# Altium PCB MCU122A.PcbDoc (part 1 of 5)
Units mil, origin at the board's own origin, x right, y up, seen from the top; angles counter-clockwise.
Board outline 4950 x 3450 mil, 4 copper layers (Top Layer, Signal Layer 1, Signal Layer 2, Bottom Layer), stack 60 mil thick; 257 components, 158 nets, 848 pads, 1971 vias.
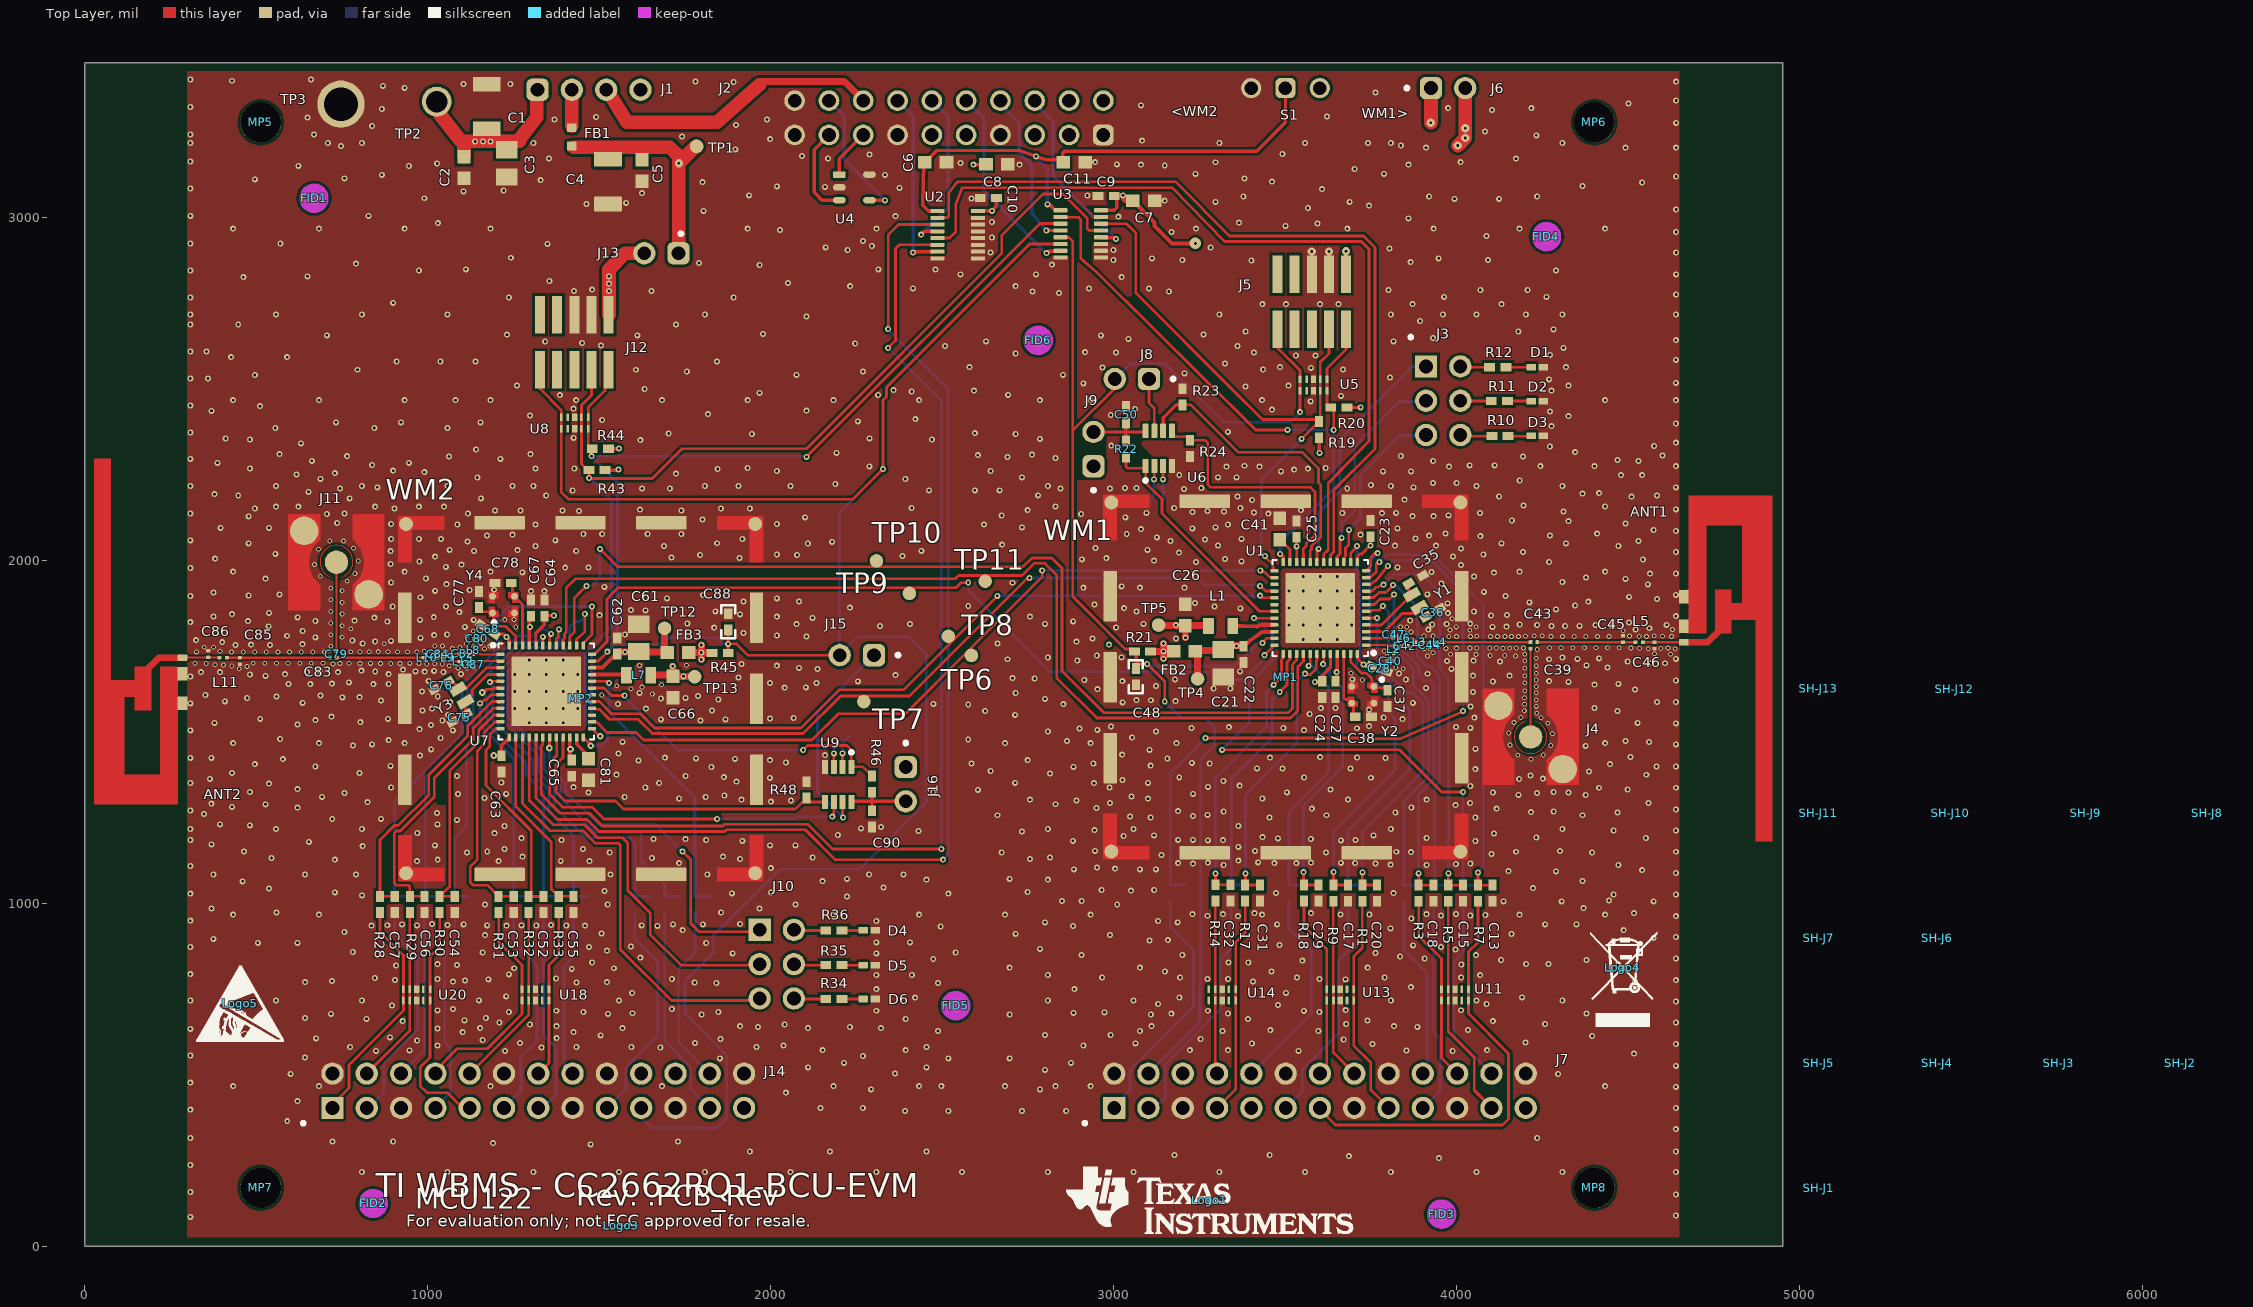
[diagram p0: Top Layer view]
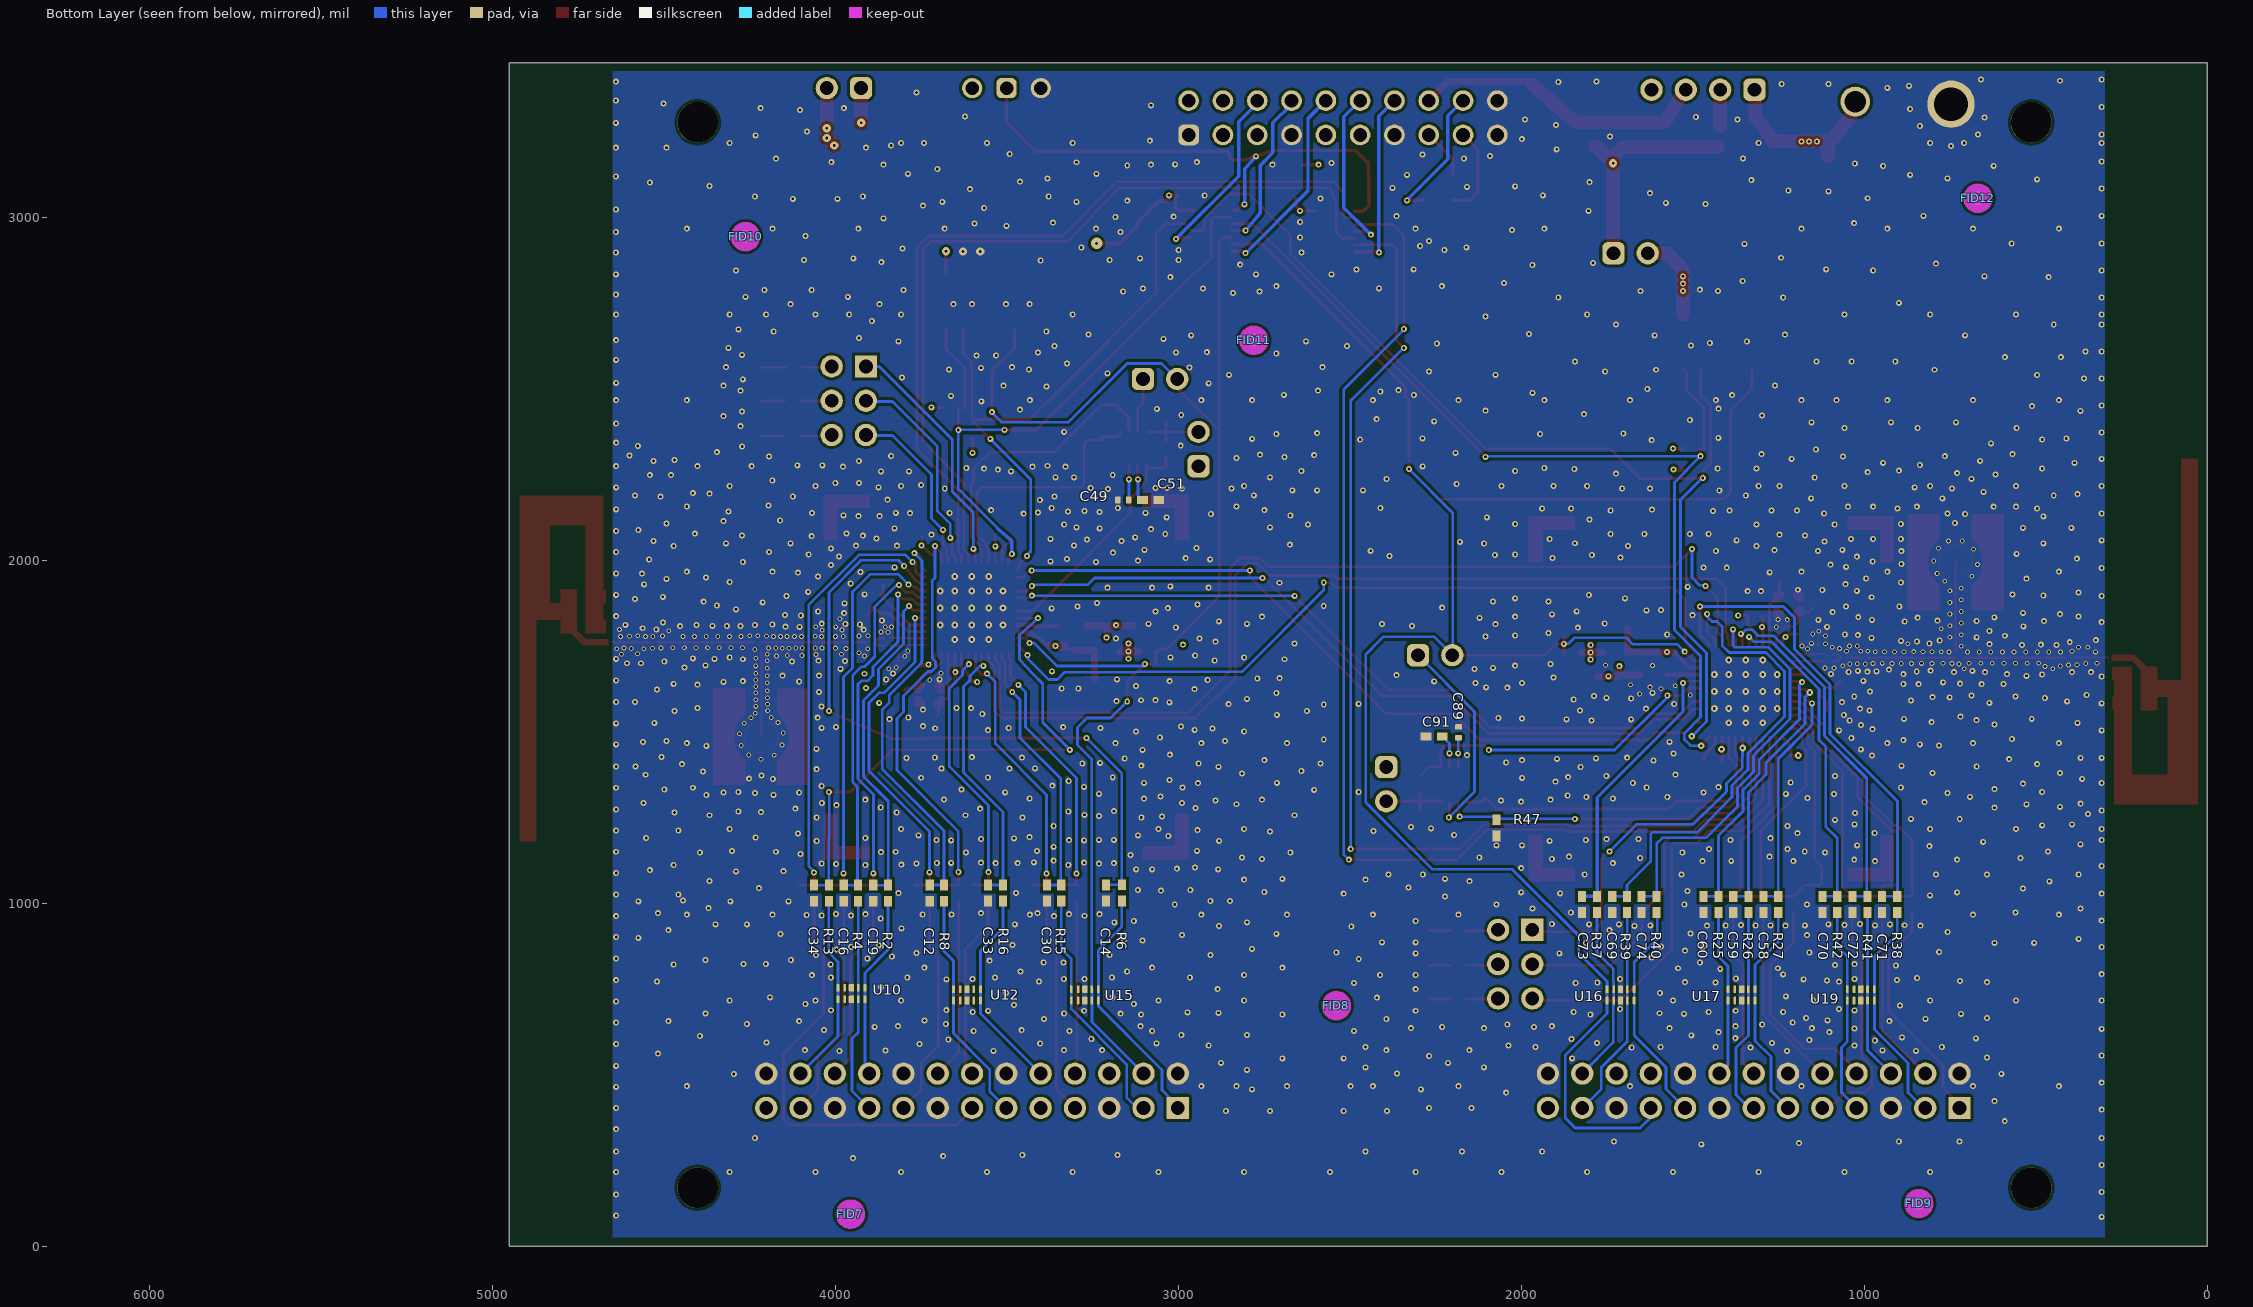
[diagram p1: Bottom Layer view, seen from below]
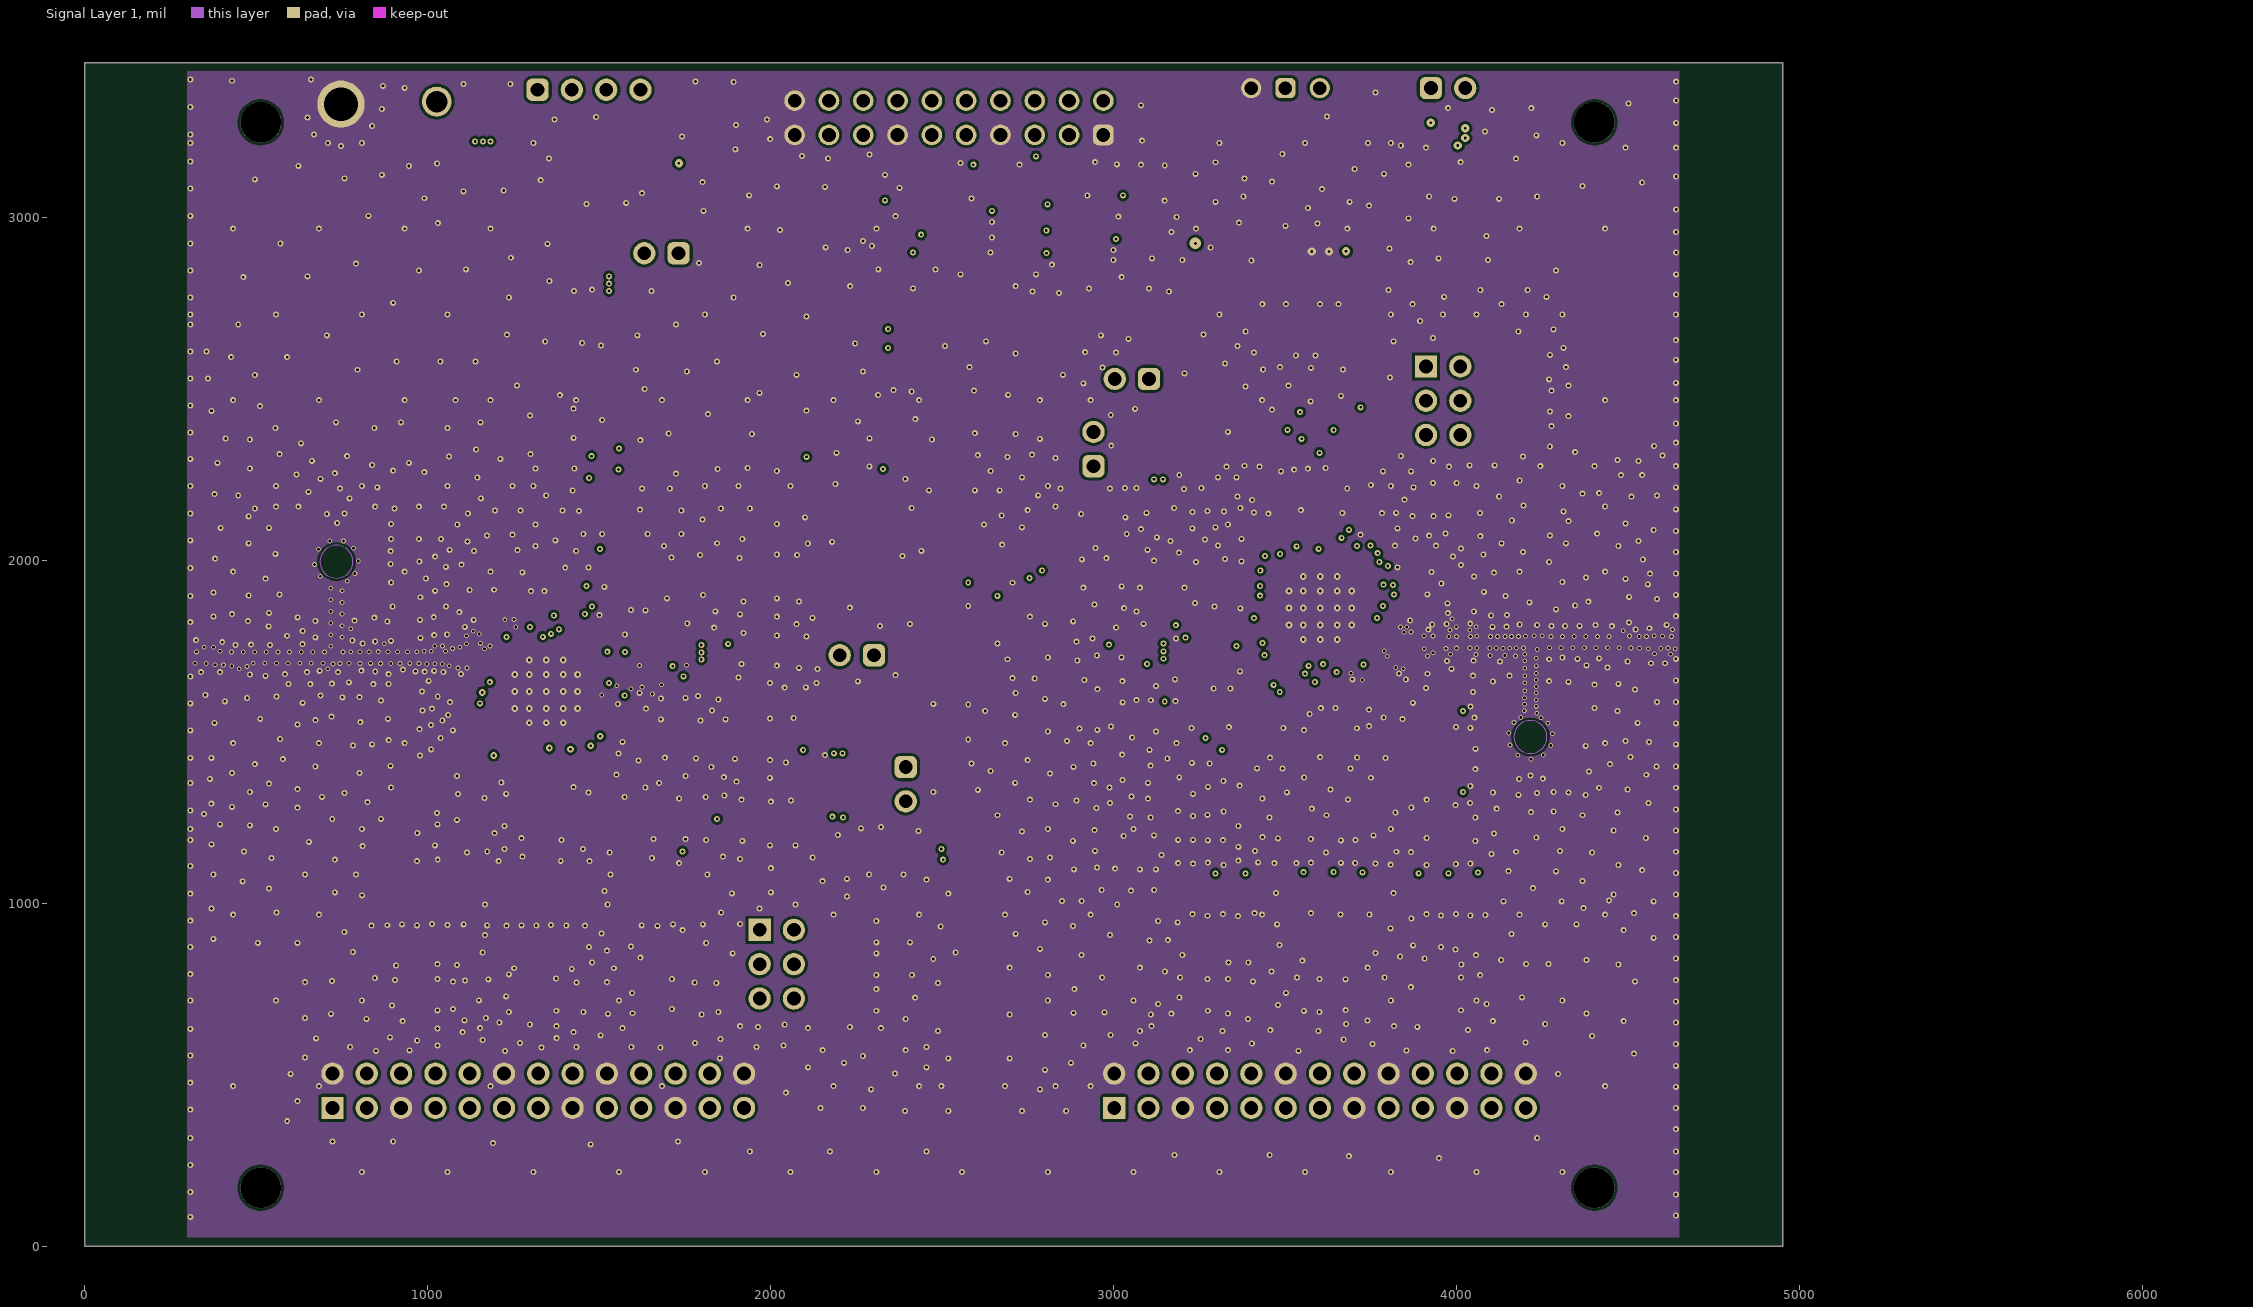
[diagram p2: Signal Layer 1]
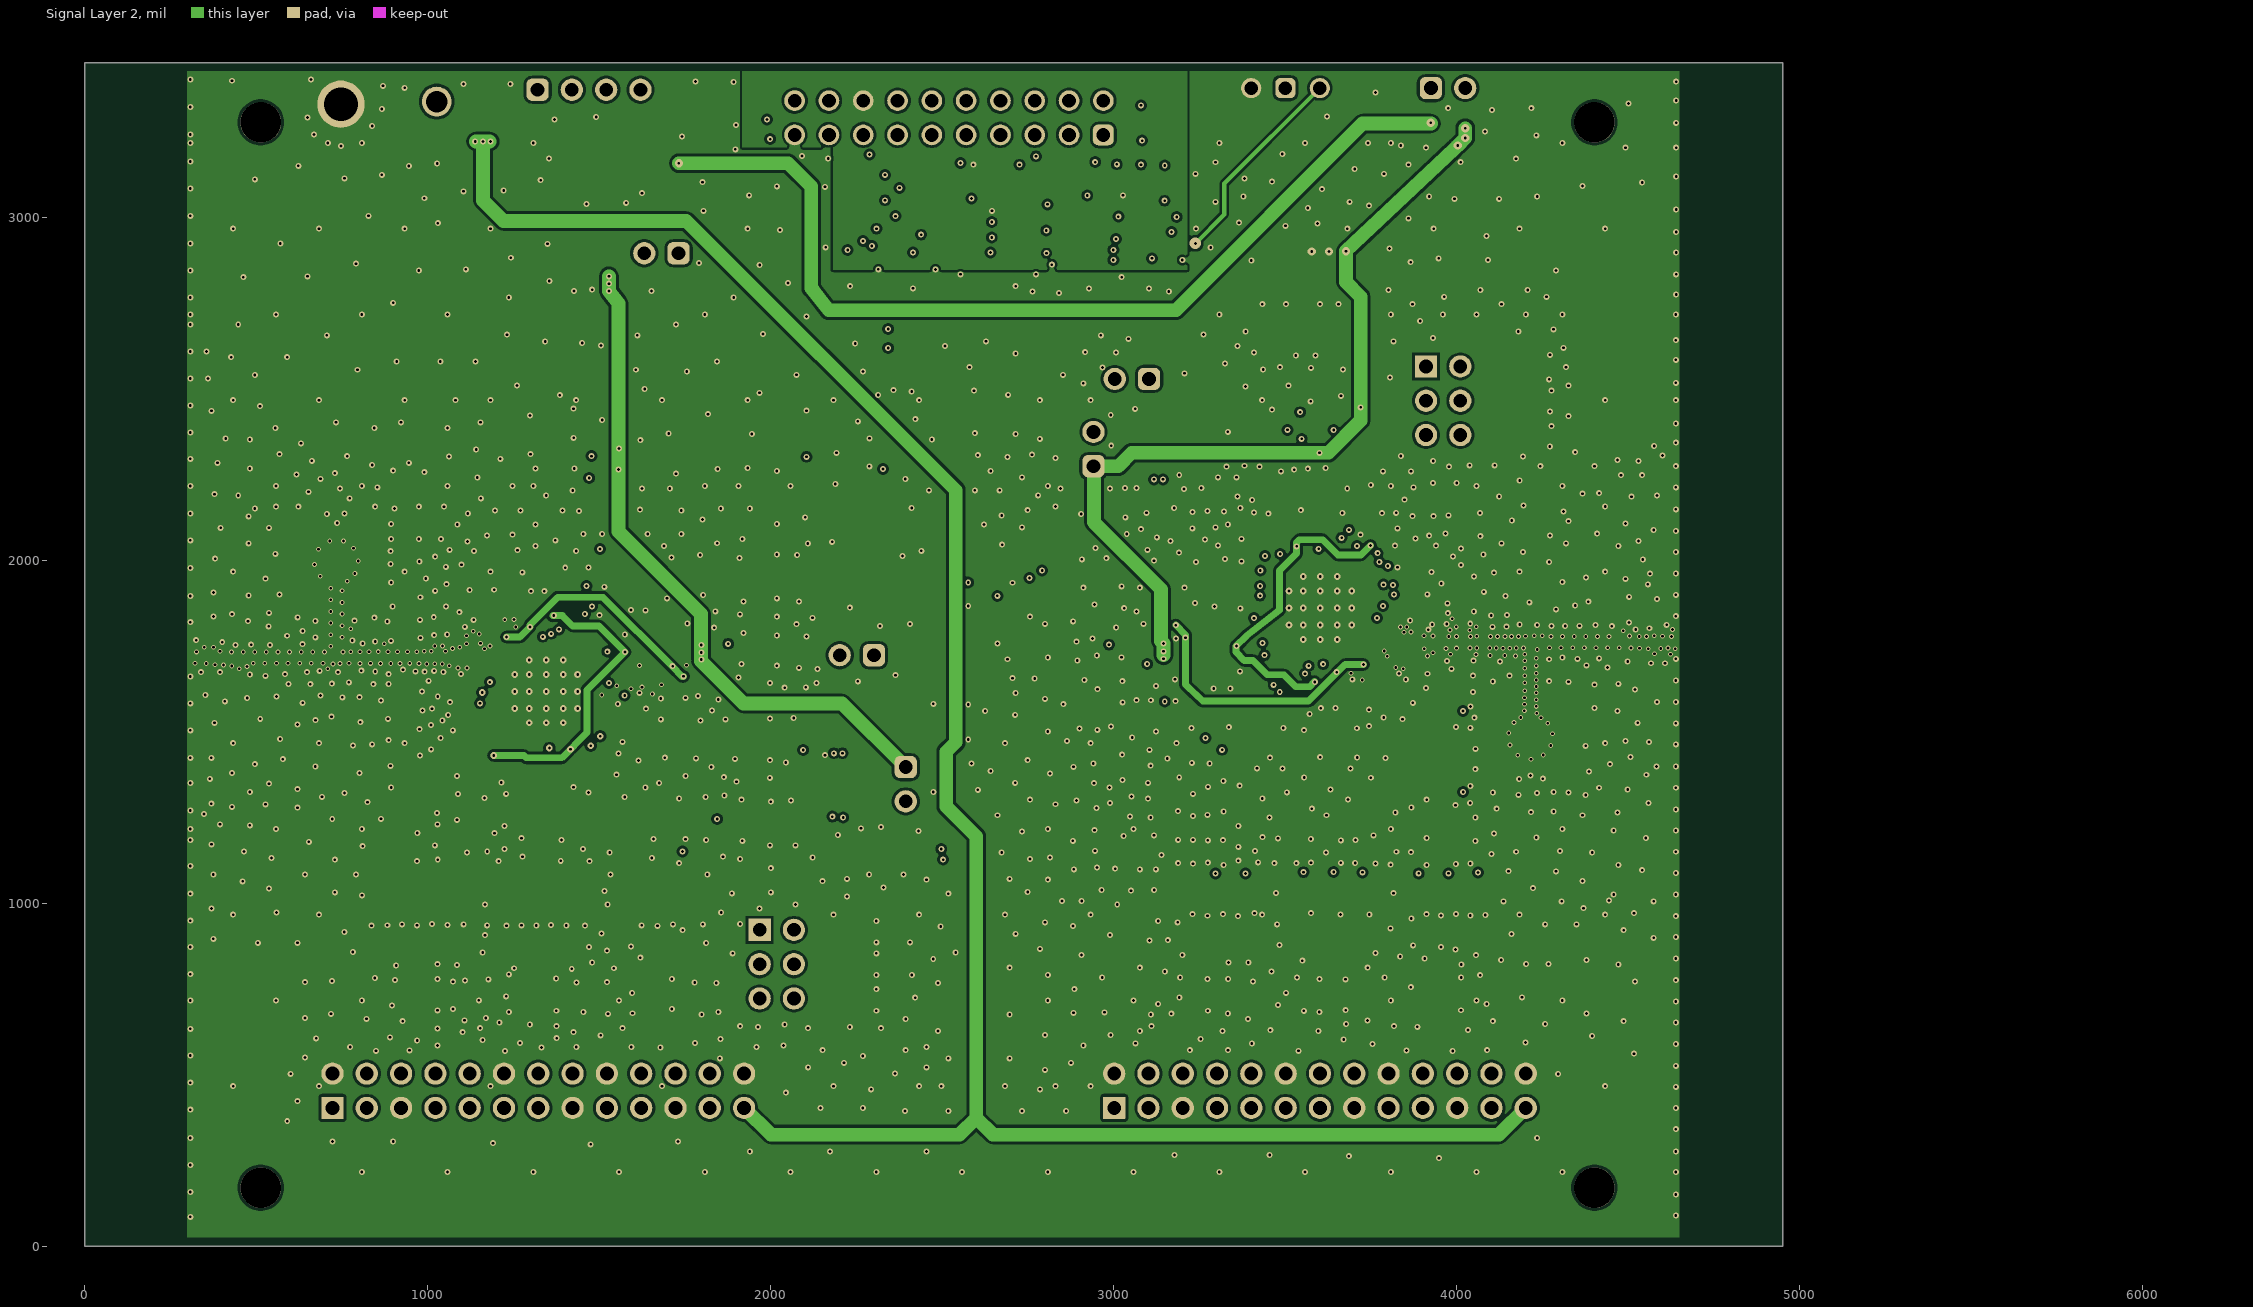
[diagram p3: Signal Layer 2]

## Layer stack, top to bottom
Top Solder: solder mask 1, Solder Resist, Dk 3.4
Top Layer: signal copper 1.6
Dielectric 1: prepreg 5, FR-4 High Tg, Dk 4.6
Signal Layer 1: signal copper 1.4
Dielectric 2: core 44, FR-4 High Tg, Dk 4.6
Signal Layer 2: signal copper 1.4
Dielectric 3: prepreg 5, FR-4 High Tg, Dk 4.6
Bottom Layer: signal copper 1.6
Bottom Solder: solder mask 1, Solder Resist, Dk 3.4

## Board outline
0,0 4950,0 4950,3450 0,3450

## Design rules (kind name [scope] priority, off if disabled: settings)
AcuteAngle [All] p1: minimum=4.50000000000000E+0001 checktracksonly=FALSE
AssemblyTestPointUsage [All] p1: valid=2
BoardOutlineClearance BoardOutlineClearance_MountingHoles [OnCopper and InComponentClass('Mounting Holes')] p1: gap=39.37 ignorepadtopadclearanceinfootprint=FALSE
BoardOutlineClearance BoardOutlineClearance_Poly [OnCopper and IsPoly] p2: gap=25 ignorepadtopadclearanceinfootprint=FALSE
BoardOutlineClearance [OnCopper and Not InComponentClass('Logo') and not InComponentClass('FiducialMark') and not InRegion(1000,500,4000,800) and not InPoly] p3: gap=30 ignorepadtopadclearanceinfootprint=FALSE
Clearance RF_GND_Clearance [InNetClass('RF') vs InNet('GND')] p1: gap=6.07 ignorepadtopadclearanceinfootprint=TRUE
Clearance Clearance_1 [All] p2: gap=7.87 ignorepadtopadclearanceinfootprint=TRUE
Clearance Clearance_FiducialMark [IsKeepOut and InComponentClass('FiducialMark') vs IsPad and InComponentClass('FiducialMark')] p3: gap=0 ignorepadtopadclearanceinfootprint=TRUE
Clearance Clearance_Keepouts [((IsTrack Or IsArc) And Not InPoly) And IsFree and IsKeepOut vs ((IsTrack Or IsArc) And Not InPoly) And IsFree and IsKeepOut] p4: gap=0 ignorepadtopadclearanceinfootprint=TRUE
ComponentClearance ComponentClearance_MountingHoles_FiducialMarks [InComponentClass('Mounting Holes') vs InComponentClass('FiducialMark')] p1: gap=50 collisioncheckmode=3 verticalgap=10 showdistances=FALSE
ComponentClearance ComponentClearance_Shunt [InComponentClass('Header') vs InComponentClass('Shunt')] p2: gap=0 collisioncheckmode=3 verticalgap=0 showdistances=FALSE
ComponentClearance ComponentClearance_Logo [InComponentClass('Logo')] p3: gap=30 collisioncheckmode=3 verticalgap=10 showdistances=FALSE
ComponentClearance ComponentClearance_ScrewToNut [(HasFootprint('NY PMS 440 0025 PH')) vs (HasFootprint('Keystone_1902C'))] p4: gap=5 collisioncheckmode=3 verticalgap=10 showdistances=FALSE
ComponentClearance ComponentClearance_MountingHoles [InComponentClass('Mounting Holes')] p5: gap=100 collisioncheckmode=3 verticalgap=100000 showdistances=FALSE
ComponentClearance ComponentClearance_SmallPassives [HasFootprint('0201*') or HasFootprint('0402*') or HasFootprint('0508') or HasFootprint('0603*') or HasFootprint('0612') or HasFootprint('0805*') or HasFootprint('0815*') or HasFootprint('0830*') or HasFootprint('1206*') or HasFootprint('1210*') or HasFootprint('1808*') or HasFootprint('1812*') or HasFootprint('1825*') or HasFootprint('2010*') or HasFootprint('2220*') or HasFootprint('2225*') or HasFootprint('2512*') or HasFootprint('2728*') or HasFootprint('3518*') vs HasFootprint('0201*') or HasFootprint('0402*') or HasFootprint('0508') or HasFootprint('0603*') or HasFootprint('0612') or HasFootprint('0805*') or HasFootprint('0815*') or HasFootprint('0830*') or HasFootprint('1206*') or HasFootprint('1210*') or HasFootprint('1808*') or HasFootprint('1812*') or HasFootprint('1825*') or HasFootprint('2010*') or HasFootprint('2220*') or HasFootprint('2225*') or HasFootprint('2512*') or HasFootprint('2728*') or HasFootprint('3518*')] p6: gap=14.96 collisioncheckmode=3 verticalgap=10 showdistances=FALSE
ComponentClearance ComponentClearance_THtoSMT [IsThruComponent vs IsSMTComponent] p7: gap=30 collisioncheckmode=3 verticalgap=30 showdistances=FALSE
ComponentClearance ComponentClearance_THtoTH [IsThruComponent vs IsThruComponent] p8: gap=20 collisioncheckmode=3 verticalgap=30 showdistances=FALSE
ComponentClearance [All] p9: gap=10 collisioncheckmode=3 verticalgap=10 showdistances=FALSE
DiffPairsRouting [All] p1: maxlimit=100 minlimit=10 mostfreqgap=10 toplayer_minwidth=15 toplayer_maxwidth=15 toplayer_prefwidth=15 midlayer1_minwidth=15 midlayer1_maxwidth=15 midlayer1_prefwidth=15 midlayer2_minwidth=15 midlayer2_maxwidth=15 midlayer2_prefwidth=15 bottomlayer_minwidth=15 bottomlayer_maxwidth=15 bottomlayer_prefwidth=15 maxuncoupledlength=1000
FabricationTestPointUsage TestPointUsage [All] p1: valid=2 allowmultiple=FALSE
FabricationTestpoint Testpoint [All] p1: side=3 testpointundercomponent=TRUE minsize=40 maxsize=100 preferedsize=60 minholesize=0 maxholesize=40 preferedholesize=32 testpointgrid=1 allowsidetop=TRUE allowsidebottom=TRUE usegrid=TRUE gridtolerance=0.01
FanoutControl Fanout_LCC [IsLCC] p1: bgadir=Out bgaviamode=Centered fanoutstyle=Auto fanoutdirection=Alternating viagrid=1 // Fanout_LCC (Default Rule)
FanoutControl Fanout_BGA [IsBGA] p2: bgadir=Out bgaviamode=Centered fanoutstyle=Auto fanoutdirection=Alternating viagrid=1 // Fanout_BGA (Default Rule)
FanoutControl Fanout_Default [All] p4: bgadir=Out bgaviamode=Centered fanoutstyle=Auto fanoutdirection=Alternating viagrid=1 // Fanout_Default (Default Rule)
FanoutControl Fanout_Small [(CompPinCount < 5)] p5: bgadir=Out bgaviamode=Centered fanoutstyle=Auto fanoutdirection=OutThenIn viagrid=1 // Fanout_Small (Default Rule)
HoleSize [All] p1: absolutevalues=TRUE maxlimit=251 minlimit=8 maxpercent=80.000 minpercent=20.000
MinimumAnnularRing MinimumAnnularRing_ThermalPadVias [IsVia and InAnyComponent] p1: minimumring=5.9
MinimumAnnularRing [All] p2: minimumring=2.9
MinimumSolderMaskSliver MinimumSolderMaskSliver_Logo [InComponentClass('Logo') vs InComponentClass('Logo')] p1: minsoldermaskwidth=0.7
MinimumSolderMaskSliver [All] p2: minsoldermaskwidth=3.94
PlaneClearance PlaneClearance_1 [All] p1: clearance=20
PlaneClearance [InNet('3V3_XDS') And OnLayer('Signal Layer 2')] p2: clearance=0
PlaneConnect [InNet('3V3_XDS') And OnLayer('Signal Layer 2')] p1: planeconnectstyle=Direct reliefexpansion=10 reliefentries=4 reliefconductorwidth=10 reliefairgap=10
PlaneConnect PlaneConnect_1 [All] p2: planeconnectstyle=Direct reliefexpansion=20 reliefentries=4 reliefconductorwidth=10 reliefairgap=10
PolygonConnect [All] p1: connectstyle=Direct reliefconductorwidth=10 reliefentries=4 polygonreliefangle="90 Angle" airgapwidth=10
RoutingVias ThermalPadVias [IsVia and InAnyComponent] p1: holewidth=7.87 width=19.68 viastyle="Through Hole" minholewidth=5.87 minwidth=11.4 maxholewidth=12.99 maxwidth=23.62
RoutingVias [All] p2: holewidth=16 width=34 viastyle="Through Hole" minholewidth=5.87 minwidth=11.4 maxholewidth=40 maxwidth=65
SilkToBoardRegionClearance [Not ((IsComment or IsDesignator) And (Hide <> 'False')) and not InRegion(1000,500,4000,800)] p1:
SilkToSilkClearance SilkToSilkClearance_Pb-FreeLogo [(HasFootprint('Pb-Free_Overlay_Medium') OR HasFootprint('Pb-Free_Overlay_Small')) vs (HasFootprint('Pb-Free_Overlay_Medium') OR HasFootprint('Pb-Free_Overlay_Small'))] p1: silktosilkclearance=0
SilkToSilkClearance [All] p2: silktosilkclearance=3.94
SilkToSolderMaskClearance SilkToComponentPadClearance [(IsPad or IsFill or IsRegion) and InAnycomponent] p1: minsilkscreentomaskgap=5 clearancetoexposedcopper=TRUE
SilkToSolderMaskClearance "Silk to Solder Mask Opening" [All] p2: minsilkscreentomaskgap=3.94 clearancetoexposedcopper=FALSE
SolderMaskExpansion SolderMaskExpansion_2 [InPadClass('All Pads')] p1 off: expansion=8 istentingtop=FALSE
SolderMaskExpansion SolderMaskExpansion_1 [IsVia] p2: expansion=4 istentingtop=TRUE
SolderMaskExpansion [All] p3 off: expansion=-20 istentingtop=TRUE soldermaskfromhole=TRUE
SupplyNets "Schematic Supply Nets_13" [InNet('VDDR_WM2')] p1: voltage=0.000
SupplyNets "Schematic Supply Nets_12" [InNet('5V0_BP')] p2: voltage=0.000
SupplyNets "Schematic Supply Nets_11" [InNet('3V3_WM')] p3: voltage=0.000
SupplyNets "Schematic Supply Nets_10" [InNet('VDDS_WM2')] p4: voltage=0.000
SupplyNets "Schematic Supply Nets_9" [InNet('WM2_VDD')] p5: voltage=0.000
SupplyNets "Schematic Supply Nets_8" [InNet('3V3_XDS')] p6: voltage=0.000
SupplyNets "Schematic Supply Nets_7" [InNet('3V3_EXT')] p7: voltage=0.000
SupplyNets "Schematic Supply Nets_6" [InNet('VDDS_WM1')] p8: voltage=0.000
SupplyNets "Schematic Supply Nets_5" [InNet('WM1_WD_VDD')] p9: voltage=0.000
SupplyNets "Schematic Supply Nets_4" [InNet('3V3_VDD')] p10: voltage=0.000
SupplyNets "Schematic Supply Nets_3" [InNet('VDDR_WM1')] p11: voltage=0.000
SupplyNets "Schematic Supply Nets_2" [InNet('GND')] p12: voltage=0.000
SupplyNets "Schematic Supply Nets_1" [InNet('WM1_VDD')] p13: voltage=0.000
SupplyNets "Schematic Supply Nets" [InNet('WM2_WD_VDD')] p14: voltage=0.000
UnRoutedNet [All] p1 off: checkbadconnections=TRUE
Width RF [InNetClass('RF')] p1: maxlimit=6.5 minlimit=3.56 preferedwidth=6.5 toplayer_minwidth=6.5 midlayer1_maxwidth=3.68 midlayer1_prefwidth=3.68 midlayer2_maxwidth=3.68 midlayer2_prefwidth=3.68 bottomlayer_minwidth=6.5 impedanceprofiledriven=TRUE impedanceprofileid={6BF253D9-752C-47ED-B3CD-644EDC811900} impedanceprofilevalue=50.000000 minimp=50.000000 maximp=50.000000 favimp=50.000000 checkconnectedcopper=TRUE
Width [All] p2: maxlimit=100 minlimit=4 preferedwidth=10 midlayer1_minwidth=6 midlayer2_minwidth=6 bottomlayer_minwidth=6 minimp=50.000000 maximp=50.000000 favimp=50.000000 checkconnectedcopper=TRUE
13 further rules are at their usual default settings.

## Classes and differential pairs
component class MCU122A_WM2_ESD: U16 U17 U18 U19 U20
component class MCU122A_WM1_ESD: U10 U11 U12 U13 U14 U15
net class RF: NetANT1_1 NetANT2_1 NetC39_1 NetC39_2 NetC40_1 NetC42_2 NetC43_2 NetC44_2 NetC79_1 NetC79_2 NetC82_2 NetC83_2 NetC84_2 WM1_RF1_N WM1_RF1_P WM2_RF1_N WM2_RF1_P
component class MCU122A_WM2_GPIO_Header: C89 C90 C91 J14 J15 J16 R46 R47 R48 SH-J12 SH-J13 U9
component class MCU122A_WM2: ANT2 C52 C53 C54 C55 C56 C57 C58 C59 C60 C61 C62 C63 C64 C65 C66 C67 C68 C69 C70 C71 C72 C73 C74 C75 C76 C77 C78 C79 C80 C81 C82 C83 C84 C85 C86 C87 C88 D4 D5 D6 FB3 J10 J11 J12 J13 L7 L8 L9 L10 L11 L12 R25 R26 R27 R28 R29 R30 R31 R32 R33 R34 R35 R36 R37 R38 R39 R40 R41 R42 R43 R44 R45 SH-J8 SH-J9 SH-J10 SH-J11 TP12 TP13 U7 U8 Y3 Y4
component class MCU122A_Hardware: FID1 FID2 FID3 FID4 FID5 FID6 FID7 FID8 FID9 FID10 FID11 FID12 Logo1 Logo3 Logo4 Logo5 MP1 MP2 MP3 MP4 MP5 MP6 MP7 MP8 ZZ1 ZZ2 ZZ3 ZZ4
component class MCU122A_WM1_GPIO_Header: C49 C50 C51 J7 J8 J9 R22 R23 R24 SH-J6 SH-J7 U6
component class MCU122A_WM1: ANT1 C12 C13 C14 C15 C16 C17 C18 C19 C20 C21 C22 C23 C24 C25 C26 C27 C28 C29 C30 C31 C32 C33 C34 C35 C36 C37 C38 C39 C40 C41 C42 C43 C44 C45 C46 C47 C48 D1 D2 D3 FB2 J3 J4 J5 J6 L1 L2 L3 L4 L5 L6 R1 R2 R3 R4 R5 R6 R7 R8 R9 R10 R11 R12 R13 R14 R15 R16 R17 R18 R19 R20 R21 SH-J2 SH-J3 SH-J4 SH-J5 TP4 TP5 TP6 TP7 TP8 TP9 TP10 TP11 U1 U5 Y1 Y2
component class MCU122A_Connector_PWR: C1 C2 C3 C4 C5 C6 C7 C8 C9 C10 C11 FB1 J1 J2 S1 SH-J1 TP1 TP2 TP3 U2 U3 U4

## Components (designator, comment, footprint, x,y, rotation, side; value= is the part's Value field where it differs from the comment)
ANT1 "Inverted F Antenna" 0-MFG 4783.46,1684.37 r270 top
ANT2 "Inverted F Antenna" 0-MFG 164.08,1791.31 r90 top
C1 "GCM32ER71E106MA57L" FP-GCM32ER71E106MA57L_1210-MFG 1172.33,3322.3 r270 top value=10µF
C2 "GCM188R71C105KA64D" 0603 1105.83,3144.43 r270 top value=1uF
C3 "GCM21BD70J226ME36L" 0805_HV 1230.94,3156.37 r270 top value=22uF
C4 "GCM32ER71E106MA57L" FP-GCM32ER71E106MA57L_1210-MFG 1525.59,3103.35 r90 top value=10µF
C5 "GCM188R71C105KA64D" 0603 1624.51,3136.04 r270 top value=1uF
C6 "GCM188R71C105KA64D" 0603 2659.22,3153.84 r180 top value=1uF
C7 "GCM188R71C105KA64D" 0603 3087.6,3047.58 r180 top value=1uF
C8 "GCM155R71A104KA55D" 0402 2634.61,3055.07 r0 top value=0.1uF
C9 "GCM155R71A104KA55D" 0402 2978,3060.88 r0 top value=0.1uF
C10 "GCM188R71C105KA64D" 0603 2481.07,3160 r0 top value=1uF
C11 "GCM188R71C105KA64D" 0603 2885.12,3160 r0 top value=1uF
C12 "GCM155R71A104KA55D" 0402 3724.6,1028.97 r90 bottom value=0.1uF
C13 "GCM155R71A104KA55D" 0402 4104.69,1028.6 r90 top value=0.1uF
C14 "GCM155R71A104KA55D" 0402 3211.37,1029.38 r90 bottom value=0.1uF
C15 "GCM155R71A104KA55D" 0402 4018.55,1028.6 r90 top value=0.1uF
C16 "GCM155R71A104KA55D" 0402 3975.42,1028.6 r90 bottom value=0.1uF
C17 "GCM155R71A104KA55D" 0402 3683.42,1028.97 r270 top value=0.1uF
C18 "GCM155R71A104KA55D" 0402 3932.79,1028.6 r90 top value=0.1uF
C19 "GCM155R71A104KA55D" 0402 3889.51,1028.6 r90 bottom value=0.1uF
C20 "GCM155R71A104KA55D" 0402 3767.47,1028.97 r90 top value=0.1uF
C21 "GCM21BD70J226ME36L" 0805_HV 3319.9,1699.18 r270 top value=22uF
C22 "GCM155R71A104KA55D" 0402 3377.97,1724.77 r270 top value=0.1uF
C23 "GCM155R71A104KA55D" 0402 3749.03,2091.54 r90 top value=0.1uF
C24 "GCM155R71A104KA55D" 0402 3608,1623 r270 top value=0.1uF
C25 "GCM155R71A104KA55D" 0402 3533.46,2090 r90 top value=0.1uF
C26 "AMK107BBJ226MAHT" 0603 3208.54,1839.48 r90 top value=22uF
C27 "GCM155R71A104KA55D" 0402 3647,1623 r270 top value=0.1uF
C28 "GCM155R71A104KA55D" 0402 3774.41,1683 r340 top value=0.1uF
C29 "GCM155R71A104KA55D" 0402 3597.41,1029.16 r90 top value=0.1uF
C30 "GCM155R71A104KA55D" 0402 3382.95,1029.16 r90 bottom value=0.1uF
C31 "GCM155R71A104KA55D" 0402 3426.45,1029.16 r90 top value=0.1uF
C32 "GCM155R71A104KA55D" 0402 3340.52,1029.57 r90 top value=0.1uF
C33 "GCM155R71A104KA55D" 0402 3554.46,1029.16 r90 bottom value=0.1uF
C34 "GCM155R71A104KA55D" 0402 4061.83,1028.6 r90 bottom value=0.1uF
C35 "GCM1555C1H120JA16J" 0402 3881,1943 r30 top value=12pF
C36 "GCM1555C1H120JA16J" 0402 3930,1846.33 r30 top value=12pF
C37 "GCM1555C1H120JA16J" 0402 3798,1597 r270 top value=12pF
C38 "GCM1555C1H120JA16J" 0402 3728,1543 r0 top value=12pF
C39 "GCQ0335C1H1R0BB01D" FP-GCQ0335C1H1R0BB01D_0201-MFG 4215.44,1751.2 r270 top value=1pF
C40 "GCQ0335C1H120GB01D" FP-GCQ0335C1H120GB01D_0201-MFG 3806.5,1705 r180 top value=12pF
C41 "GCM188R71C105KA64D" 0603 3484.17,2090 r90 top value=1uF
C42 "GCQ0335C1H1R0WB01D" FP-GCQ0335C1H1R0WB01D_0201-MFG 3848,1749.3 r0 top value=1pF
C43 "GCQ0335C1H120GB01D" FP-GCQ0335C1H120GB01D_0201-MFG 4225.79,1760.54 r0 top value=12pF
C44 "GCQ0335C1H1R0WB01D" FP-GCQ0335C1H1R0WB01D_0201-MFG 3922,1751 r90 top value=1pF
C45 "GCQ0335C1HR70WB01D" FP-GCQ0335C1HR70WB01D_0201-MFG 4484.8,1769.9 r270 top value=0.7pF
C46 "GCQ0335C1H1R0BB01D" FP-GCQ0335C1H1R0BB01D_0201-MFG 4576.77,1751 r90 top value=1pF
C47 "GCQ0335C1H1R0WB01D" FP-GCQ0335C1H1R0WB01D_0201-MFG 3816.03,1782.5 r270 top value=1pF
C48 "GCM155R71A104KA55D" 0402 3064.77,1659.87 r270 top value=0.1uF
C49 "GCM155R71E473KA55D" FP-GCM155R71E473KA55D_0402-MFG 3160.62,2175.16 r0 bottom value=47nF
C50 "GCM155R71A104KA55D" 0402 3036.11,2423.59 r90 top value=0.1uF
C51 "GCM155R71E103KA37D" 0402 3080.71,2175.16 r180 bottom value=0.01uF
C52 "GCM155R71A104KA55D" 0402 1337.97,995.82 r90 top value=0.1uF
C53 "GCM155R71A104KA55D" 0402 1250.97,995.82 r90 top value=0.1uF
C54 "GCM155R71A104KA55D" 0402 1078.97,995.82 r90 top value=0.1uF
C55 "GCM155R71A104KA55D" 0402 1424.97,995.82 r270 top value=0.1uF
C56 "GCM155R71A104KA55D" 0402 990.97,995.82 r90 top value=0.1uF
C57 "GCM155R71A104KA55D" 0402 903.97,995.82 r90 top value=0.1uF
C58 "GCM155R71A104KA55D" 0402 1293.97,995.82 r90 bottom value=0.1uF
C59 "GCM155R71A104KA55D" 0402 1381.97,995.82 r90 bottom value=0.1uF
C60 "GCM155R71A104KA55D" 0402 1468.97,995.82 r90 bottom value=0.1uF
C61 "GCM21BD70J226ME36L" 0805_HV 1615.24,1772.86 r90 top value=22uF
C62 "GCM155R71A104KA55D" 0402 1552.78,1749.51 r90 top value=0.1uF
C63 "GCM155R71A104KA55D" 0402 1214.77,1405.74 r270 top value=0.1uF
C64 "GCM155R71A104KA55D" 0402 1340,1860 r90 top value=0.1uF
C65 "GCM155R71A104KA55D" 0402 1420,1393 r270 top value=0.1uF
C66 "AMK107BBJ226MAHT" 0603 1714.71,1629.43 r270 top value=22uF
C67 "GCM155R71A104KA55D" 0402 1301,1860 r90 top value=0.1uF
C68 "GCM155R71A104KA55D" 0402 1175.5,1798 r145 top value=0.1uF
C69 "GCM155R71A104KA55D" 0402 1734.97,995.82 r90 bottom value=0.1uF
C70 "GCM155R71A104KA55D" 0402 1121.73,995.82 r90 bottom value=0.1uF
C71 "GCM155R71A104KA55D" 0402 947.97,995.82 r90 bottom value=0.1uF
C72 "GCM155R71A104KA55D" 0402 1034.97,995.82 r90 bottom value=0.1uF
C73 "GCM155R71A104KA55D" 0402 1822.87,995.82 r90 bottom value=0.1uF
C74 "GCM155R71A104KA55D" 0402 1649.15,995.82 r90 bottom value=0.1uF
C75 "GCM1555C1H120JA16J" 0402 1092.6,1539.7 r210 top value=12pF
C76 "GCM1555C1H120JA16J" 0402 1040,1634 r210 top value=12pF
C77 "GCM1555C1H120JA16J" 0402 1149.5,1885 r90 top value=12pF
C78 "GCM1555C1H120JA16J" 0402 1220,1933.5 r180 top value=12pF
C79 "GCQ0335C1H1R0BB01D" FP-GCQ0335C1H1R0BB01D_0201-MFG 734,1724.7 r90 top value=1pF
C80 "GCQ0335C1H120GB01D" FP-GCQ0335C1H120GB01D_0201-MFG 1142.8,1770 r0 top value=12pF
C81 "GCM188R71C105KA64D" 0603 1468.5,1389 r270 top value=1uF
C82 "GCQ0335C1H1R0WB01D" FP-GCQ0335C1H1R0WB01D_0201-MFG 1101.6,1726.45 r180 top value=1pF
C83 "GCQ0335C1H120GB01D" FP-GCQ0335C1H120GB01D_0201-MFG 723.65,1715.3 r180 top value=12pF
C84 "GCQ0335C1H1R0WB01D" FP-GCQ0335C1H1R0WB01D_0201-MFG 1029,1724.75 r270 top value=1pF
C85 "GCQ0335C1HR70WB01D" FP-GCQ0335C1HR70WB01D_0201-MFG 452.23,1705.5 r90 top value=0.7pF
C86 "GCQ0335C1H1R0BB01D" FP-GCQ0335C1H1R0BB01D_0201-MFG 360.23,1726 r270 top value=1pF
C87 "GCQ0335C1H1R0WB01D" FP-GCQ0335C1H1R0WB01D_0201-MFG 1133.36,1694.77 r90 top value=1pF
C88 "GCM155R71A104KA55D" 0402 1876.19,1820.04 r90 top value=0.1uF
C89 "GCM155R71E473KA55D" FP-GCM155R71E473KA55D_0402-MFG 2183,1497.64 r90 bottom value=47nF
C90 "GCM155R71A104KA55D" 0402 2295.28,1245.36 r270 top value=0.1uF
C91 "GCM155R71E103KA37D" 0402 2253.84,1485.9 r0 bottom value=0.01uF
D1 "APHHS1005LZGCK-V" FP-APHHS1005LZGCK-V_0402-MFG 4235.14,2562.21 r180 top
D2 "APHHS1005LSECK/J4-PF" FP-APHHS1005LSECK/J4-PF_0402-MFG 4235.14,2462.71 r180 top
D3 "APHHS1005LSECK/J3-PF" FP-APHHS1005LSECK/J3-PF_0402-MFG 4234.77,2362.21 r180 top
D4 "APHHS1005LZGCK-V" FP-APHHS1005LZGCK-V_0402-MFG 2287.19,920.49 r180 top
D5 "APHHS1005LSECK/J4-PF" FP-APHHS1005LSECK/J4-PF_0402-MFG 2287.19,818.9 r180 top
D6 "APHHS1005LSECK/J3-PF" FP-APHHS1005LSECK/J3-PF_0402-MFG 2287.19,720.48 r180 top
FB1 "BLM18HE152SH1D" FP-BLM18HE152SH1D_0603-MFG 1419.5,3233.84 r270 top
FB2 "BLM18HE152SZ1D" 0603 3206.05,1733.88 r0 top value="1500 ohm"
FB3 "BLM18HE152SZ1D" 0603 1729.36,1730.36 r180 top value="1500 ohm"
FID1 "Fiducial" Fiducial10-20 668.63,3054.8 r0 top
FID2 "Fiducial" Fiducial10-20 841.28,124.02 r0 top
FID3 "Fiducial" Fiducial10-20 3955.88,93.11 r0 top
FID4 "Fiducial" Fiducial10-20 4261.81,2942.91 r0 top
FID5 "Fiducial" Fiducial10-20 2539.37,700.73 r0 top
FID6 "Fiducial" Fiducial10-20 2779.81,2640.67 r0 top
FID7 "Fiducial" Fiducial10-20 3955.88,93.11 r180 bottom
FID8 "Fiducial" Fiducial10-20 2539.37,700.73 r180 bottom
FID9 "Fiducial" Fiducial10-20 841.28,124.02 r180 bottom
FID10 "Fiducial" Fiducial10-20 4261.81,2942.91 r180 bottom
FID11 "Fiducial" Fiducial10-20 2779.81,2640.67 r180 bottom
FID12 "Fiducial" Fiducial10-20 668.63,3054.8 r180 bottom
J1 "TSW-104-07-G-S" TSW-104-07-G-S 1470.39,3371.2 r0 top
J2 "SFH11-PBPC-D10-RA-BK" Sullins_SFH11-xxxC-D10-RA 2519.88,3289.36 r180 top
J3 "TSW-103-07-G-D" TSW-103-07-G-D 3960.73,2464.54 r270 top
J4 "132134-10" FP-132134-10_SMA-MFG 4215.5,1484.25 r0 top
J5 "FTSH-105-01-F-DV-K" Samtec_FTSH-105-01-x-DV-K 3577.56,2752.76 r270 top
J6 "TSW-102-07-G-S" TSW-102-07-G-S 3974.8,3375.98 r0 top
J7 "TSW-113-07-G-D" TSW-113-07-G-D 3601.38,452.76 r0 top
J8 "TSW-102-07-G-S" TSW-102-07-G-S 3053.15,2528 r180 top
J9 "TSW-102-07-G-S" TSW-102-07-G-S 2941.14,2323.59 r90 top
J10 "TSW-103-07-G-D" TSW-103-07-G-D 2017.72,821.8 r270 top
J11 "132134-10" FP-132134-10_SMA-MFG 734,1993.6 r0 top
J12 "FTSH-105-01-F-DV-K" Samtec_FTSH-105-01-x-DV-K 1427.37,2634.9 r270 top
J13 "TSW-102-07-G-S" TSW-102-07-G-S 1681.5,2894.48 r180 top
J14 "TSW-113-07-G-D" TSW-113-07-G-D 1322.44,452.76 r0 top
J15 "TSW-102-07-G-S" TSW-102-07-G-S 2251.14,1722.67 r180 top
J16 "TSW-102-07-G-S" TSW-102-07-G-S 2393.7,1346.39 r270 top
L1 "MLZ2012N6R8LTD25" FP-MLZ2012N6R8LTD25_0805-MFG 3311.47,1808 r180 top value=6.8uH
L2 "LQP03TN3N7BZ2J" FP-LQP03TN3N7BZ2J_0603-MFG 3816.03,1739.3 r270 top value=3.7nH
L3 "LQP03TN3N4BZ2B" "FP-LQP03TN3N4BZ2B_0201 (0603)-MFG" 3891.19,1760.3 r0 top value=3.4nH
L4 "LQP03TN3N4BZ2B" "FP-LQP03TN3N4BZ2B_0201 (0603)-MFG" 3951,1760.37 r0 top value=3.4nH
L5 "LQP03TN1N9BZ2B" "FP-LQP03TN1N9BZ2B_0201 (0603)-MFG" 4532,1760.5 r0 top value=1.9nH
L6 "LQP03TN3N7BZ2J" FP-LQP03TN3N7BZ2J_0603-MFG 3846,1772.3 r0 top value=3.7nH
L7 "MLZ2012N6R8LTD25" FP-MLZ2012N6R8LTD25_0805-MFG 1615,1664.38 r0 top value=6.8uH
L8 "LQP03TN3N7BZ2J" FP-LQP03TN3N7BZ2J_0603-MFG 1133.36,1737.27 r90 top value=3.7nH
L9 "LQP03TN3N4BZ2B" "FP-LQP03TN3N4BZ2B_0201 (0603)-MFG" 1059,1715.4 r180 top value=3.4nH
L10 "LQP03TN3N4BZ2B" "FP-LQP03TN3N4BZ2B_0201 (0603)-MFG" 999,1715.4 r180 top value=3.4nH
L11 "LQP03TN1N9BZ2B" "FP-LQP03TN1N9BZ2B_0201 (0603)-MFG" 404,1715.5 r180 top value=1.9nH
L12 "LQP03TN3N7BZ2J" FP-LQP03TN3N7BZ2J_0603-MFG 1104.14,1704.02 r180 top value=3.7nH
Logo1 "Texas Instruments" TI_Stacked_Overlay_Small 3279.9,133.74 r0 top
Logo3 "FCC disclaimer" FCC_disclaimer 1564.96,59.06 r0 top
Logo4 "WEEE logo" WEEE_Minimum 4484.8,811.6 r0 top
Logo5 "ESD Susceptible" ESD_Overlay_Medium 454.05,705.97 r0 top
MP1 "SMS-403F" FP-SMS-403F_SMT_SHIELD-MFG 3502,1659 r0 top
MP2 "SMS-403F" FP-SMS-403F_SMT_SHIELD-MFG 1446,1596 r0 top locked
MP3 "SMS-403C" FP-SMS-403C_RF_SHLD-MFG 7155.51,954.72 r0 top
MP4 "SMS-403C" FP-SMS-403C_RF_SHLD-MFG 8366.14,944.88 r0 top
MP5 "DCB-12D" FP-DCB-12D_SPACER-MFG 513.09,3276.06 r0 top
MP6 "DCB-12D" FP-DCB-12D_SPACER-MFG 4401.49,3276.06 r0 top
MP7 "DCB-12D" FP-DCB-12D_SPACER-MFG 513.09,170.11 r0 top
MP8 "DCB-12D" FP-DCB-12D_SPACER-MFG 4401.49,170.11 r0 top
R1 "CRCW04020000Z0ED" 0402 3724.87,1028.79 r270 top value=0
R2 "CRCW04020000Z0ED" 0402 3846.14,1028.6 r270 bottom value=0
R3 "CRCW04020000Z0ED" 0402 3889.25,1028.6 r270 top value=0
R4 "CRCW04020000Z0ED" 0402 3933.44,1028.6 r270 bottom value=0
R5 "CRCW04020000Z0ED" 0402 3975.42,1028.6 r270 top value=0
R6 "CRCW04020000Z0ED" 0402 3164.74,1029.55 r270 bottom value=0
R7 "CRCW04020000Z0ED" 0402 4061.86,1028.6 r270 top value=0
R8 "CRCW04020000Z0ED" 0402 3682.93,1028.97 r270 bottom value=0
R9 "CRCW04020000Z0ED" 0402 3640.76,1028.97 r270 top value=0
R10 "CRCW04023K00JNED" 0402 4126.34,2361.29 r0 top value=3.0k
R11 "CRCW04023K00JNED" 0402 4124.27,2463.62 r0 top value=3.0k
R12 "CRCW04023K00JNED" 0402 4119.72,2562.21 r0 top value=3.0k
R13 "CRCW04020000Z0ED" 0402 4018.88,1028.6 r270 bottom value=0
R14 "CRCW04020000Z0ED" 0402 3296.27,1029.57 r270 top value=0
R15 "CRCW04020000Z0ED" 0402 3341.36,1029.16 r270 bottom value=0
R16 "CRCW04020000Z0ED" 0402 3511.35,1029.16 r270 bottom value=0
R17 "CRCW04020000Z0ED" 0402 3383.39,1029.16 r270 top value=0
R18 "CRCW04020000Z0ED" 0402 3554.61,1029.16 r270 top value=0
R19 "AC0402FR-07100KL" 0402 3598.85,2380.28 r270 top value=100k
R20 "AC0402FR-07100KL" 0402 3656.48,2445.24 r0 top value=100k
R21 "AC0402FR-07100KL" 0402 3084.13,1733.87 r0 top value=100k
R22 "AC0402FR-0710KL" 0402 3036.11,2323.59 r90 top value=10.0k
R23 "AC0402FR-0710KL" 0402 3200.1,2476.06 r270 top value=10.0k
R24 "AC0402FR-0710KL" 0402 3222.5,2325.56 r90 top value=10.0k
R25 "CRCW04020000Z0ED" 0402 1424.97,995.82 r270 bottom value=0
R26 "CRCW04020000Z0ED" 0402 1337.97,995.82 r270 bottom value=0
R27 "CRCW04020000Z0ED" 0402 1250.97,995.82 r270 bottom value=0
R28 "CRCW04020000Z0ED" 0402 860.97,995.82 r270 top value=0
R29 "CRCW04020000Z0ED" 0402 947.97,995.82 r270 top value=0
R30 "CRCW04020000Z0ED" 0402 1034.97,995.82 r270 top value=0
R31 "CRCW04020000Z0ED" 0402 1206.97,995.82 r270 top value=0
R32 "CRCW04020000Z0ED" 0402 1293.97,995.82 r270 top value=0
R33 "CRCW04020000Z0ED" 0402 1381.97,995.82 r270 top value=0
R34 "CRCW04023K00JNED" 0402 2184.05,720.48 r0 top value=3.0k
R35 "CRCW04023K00JNED" 0402 2184.05,818.9 r0 top value=3.0k
R36 "CRCW04023K00JNED" 0402 2184.05,920.01 r0 top value=3.0k
R37 "CRCW04020000Z0ED" 0402 1779.02,995.82 r270 bottom value=0
R38 "CRCW04020000Z0ED" 0402 903.97,995.82 r270 bottom value=0
R39 "CRCW04020000Z0ED" 0402 1691.97,995.82 r270 bottom value=0
R40 "CRCW04020000Z0ED" 0402 1605.46,995.82 r270 bottom value=0
R41 "CRCW04020000Z0ED" 0402 990.97,995.82 r270 bottom value=0
R42 "CRCW04020000Z0ED" 0402 1078.97,995.82 r270 bottom value=0
R43 "AC0402FR-07100KL" 0402 1493.69,2262.29 r0 top value=100k
R44 "AC0402FR-07100KL" 0402 1503.15,2324.51 r0 top value=100k
R45 "AC0402FR-07100KL" 0402 1852.53,1728.73 r180 top value=100k
R46 "AC0402FR-0710KL" 0402 2295.28,1346.63 r270 top value=10.0k
R47 "AC0402FR-0710KL" 0402 2072.01,1219.13 r90 bottom value=10.0k
R48 "AC0402FR-0710KL" 0402 2104.33,1330.07 r270 top value=10.0k
S1 "CL-SA-12C-22" SW_CL-SA-12C-22 3500.9,3375.98 r0 top
SH-J1 "SNT-100-BK-G" SNT-100-BK-G 5056.02,168.75 r90 top value=1x2
SH-J2 "SNT-100-BK-G" SNT-100-BK-G 6109.17,532.93 r90 top value=1x2
SH-J3 "SNT-100-BK-G" SNT-100-BK-G 5754.84,532.93 r90 top value=1x2
SH-J4 "SNT-100-BK-G" SNT-100-BK-G 5400.51,532.93 r90 top value=1x2
SH-J5 "SNT-100-BK-G" SNT-100-BK-G 5056.02,532.93 r90 top value=1x2
SH-J6 "SNT-100-BK-G" SNT-100-BK-G 5400.51,897.1 r90 top value=1x2
SH-J7 "SNT-100-BK-G" SNT-100-BK-G 5056.02,897.1 r90 top value=1x2
SH-J8 "SNT-100-BK-G" SNT-100-BK-G 6187.91,1261.27 r90 top value=1x2
SH-J9 "SNT-100-BK-G" SNT-100-BK-G 5833.58,1261.27 r90 top value=1x2
SH-J10 "SNT-100-BK-G" SNT-100-BK-G 5439.88,1261.27 r90 top value=1x2
SH-J11 "SNT-100-BK-G" SNT-100-BK-G 5056.02,1261.27 r90 top value=1x2
SH-J12 "SNT-100-BK-G" SNT-100-BK-G 5452.76,1624.02 r90 top value=1x2
SH-J13 "SNT-100-BK-G" SNT-100-BK-G 5056.02,1625.44 r90 top value=1x2
TP1 "TP_SM_1MM" TP_SM_1MM#1 1783.98,3205.93 r0 top
TP2 "5012" Keystone5012 1026.51,3336.61 r0 top
TP3 "GND" Keystone1598-2 747.05,3329.06 r0 top
TP4 "TP_SM_1MM" TP_SM_1MM#2 3241.64,1653.57 r0 top
TP5 "TP_SM_1MM" TP_SM_1MM#3 3169.9,1810.38 r0 top
TP6 "TP_SM_1MM" TP_SM_1MM#1 2585.19,1721.92 r90 top
TP7 "TP_SM_1MM" TP_SM_1MM#4 2323.49,1587.35 r90 top
TP8 "TP_SM_1MM" TP_SM_1MM#1 2518.02,1777.67 r90 top
TP9 "TP_SM_1MM" TP_SM_1MM#1 2404.32,1902.68 r90 top
TP10 "TP_SM_1MM" TP_SM_1MM#1 2308.43,1997.37 r90 top
TP11 "TP_SM_1MM" TP_SM_1MM#1 2625.43,1938.08 r90 top
TP12 "TP_SM_1MM" TP_SM_1MM#1 1690.46,1801.06 r0 top
TP13 "TP_SM_1MM" TP_SM_1MM#1 1778.29,1659.75 r0 top
U1 "CC2662R1FTWRGZRQ1" RGZ0048R-MFG 3602.36,1860.24 r180 top
U2 "SN3257QDYYRQ1" DYY0016A 2544.97,2948.51 r0 top
U3 "SN3257QDYYRQ1" DYY0016A 2903.82,2950.96 r0 top
U4 "CAT24C08TDI-GT3" FP-CAT24C08TDI-GT3_TSOT-23-5-IPC_C 2244.09,3086.44 r0 top
U5 "TPD4E05U06QDQARQ1" DQA0010A#1 3582.66,2510.25 r270 top
U6 "TPS3436BDADADDFRQ1" DDF0008A-MFG 3131.22,2325.56 r90 top
U7 "CC2662R1FTWRGZRQ1" RGZ0048R-MFG 1345.58,1616.88 r0 top
U8 "TPD4E05U06QDQARQ1" DQA0010A#1 1428.4,2399.7 r270 top
U9 "TPS3436BDADADDFRQ1" DDF0008A-MFG 2196.85,1345.82 r270 top
U10 "TPD4E05U06QDQARQ1" DQA0010A#2 3953,736.06 r90 bottom
U11 "TPD4E05U06QDQARQ1" DQA0010A#1 3995.17,732.27 r90 top
U12 "TPD4E05U06QDQARQ1" DQA0010A#2 3615.99,732.27 r90 bottom
U13 "TPD4E05U06QDQARQ1" DQA0010A#1 3660.4,732.27 r90 top
U14 "TPD4E05U06QDQARQ1" DQA0010A#1 3316.14,732.27 r90 top
U15 "TPD4E05U06QDQARQ1" DQA0010A#2 3272.4,732.27 r90 bottom
U16 "TPD4E05U06QDQARQ1" DQA0010A#2 1710.72,732.27 r90 bottom
U17 "TPD4E05U06QDQARQ1" DQA0010A#2 1357.81,732.27 r90 bottom
U18 "TPD4E05U06QDQARQ1" DQA0010A#1 1314.16,732.27 r90 top
U19 "TPD4E05U06QDQARQ1" DQA0010A#2 1010.16,732.27 r90 bottom
U20 "TPD4E05U06QDQARQ1" DQA0010A#1 967.76,732.27 r90 top
Y1 "DST1610A 7BG03276AAC" "FP-DST1610A 7BG03276AAC_SMD2-MFG" 3880.5,1880.33 r300 top
Y2 "CX2016DB48000C0FRLC1" FP-CX2016DB48000C0FRLC1_SMT4_2MM05_1MM65-MFG 3726,1607 r180 top
Y3 "DST1610A 7BG03276AAC" "FP-DST1610A 7BG03276AAC_SMD2-MFG" 1098.82,1605.21 r120 top
Y4 "CX2016DB48000C0FRLC1" FP-CX2016DB48000C0FRLC1_SMT4_2MM05_1MM65-MFG 1221,1870 r0 top
ZZ1 "These assemblies are ESD sensitive, ESD precautions shall be observed." AssemblyNote 214.53,4114.55 r0 top
ZZ2 "These assemblies must be clean and free from flux and all contaminants. Use of no clean flux is not acceptable." AssemblyNote 215.16,4037.23 r0 top
ZZ3 "These assemblies must comply with workmanship standards IPC-A-610 Class 2, unless otherwise specified." AssemblyNote 215.16,3937.23 r0 top
ZZ4 "Via in PADs must be filled" AssemblyNote 214.53,3859.91 r0 top

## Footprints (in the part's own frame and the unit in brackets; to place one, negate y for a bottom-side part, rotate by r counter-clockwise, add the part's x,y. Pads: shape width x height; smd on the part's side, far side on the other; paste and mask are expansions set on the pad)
0-MFG [mm]
  rrect22% 0.46x0.74 smd paste-1000 mask-1000: 1(-1.93,-3.085)
  rrect14% 1x0.74 smd paste-1000 mask-1000: 2(-5.31,-3.085) 3(-3.11,-3.085)
  Top Layer region: -2.61,-2.715 -12.79,-2.715 -12.79,3.455 12.79,3.455 12.79,2.245 -3.61,2.245 -3.61,0.445 -2.61,0.445 -2.61,-0.325 -1.7,-1.235 -1.7,-2.715 -2.16,-2.715 -2.16,-1.425 -2.82,-0.765 -5.81,-0.765 -5.81,0.445 -4.81,0.445 -4.81,1.245 -10.61,1.245 -10.61,-1.425 -2.61,-1.425
0402 [mm] "0402 from SM-752 data"
  rect 0.8x0.6 smd: 1(-0.6,0) 2(0.6,0)
  body extent -0.55,-0.3 0.55,0.3, height 0.6
0603 [mm] "0603 from SM-752 data"
  rect 1x0.95 smd: 1(-0.8,0) 2(0.8,0)
  body extent -0.87,-0.47 0.87,0.47, height 1
0805_HV [mil] "0805 with 30mil clearance between pads"
  rect 50x63 smd: 1(-40,0) 2(40,0)
  body extent -43,-29 43,29, height 57
AssemblyNote [mil] "Assembly Note"
DDF0008A-MFG [mm]
  rrect22% 1.05x0.45 smd paste+0 mask+0: 1(-1.3,0.975) 2(-1.3,0.325) 3(-1.3,-0.325) 4(-1.3,-0.975) 5(1.3,-0.975) 6(1.3,-0.325) 7(1.3,0.325) 8(1.3,0.975)
  silkscreen extent -2.5,0.85 -2.25,1.1, body extent -1.92,-1.73 1.92,1.73, height 0.25
DQA0010A#1 [mm] "SON, 10-Leads, Body 1x2.5mm, Pitch 0.5mm, TI Recommended"
  rrect50% 0.565x0.2 smd: 1(-0.417,1) 2(-0.417,0.5) 4(-0.417,-0.5) 5(-0.417,-1) 6(0.417,-1) 7(0.417,-0.5) 9(0.417,0.5) 10(0.417,1)
  rrect28% 0.565x0.36 on Top Paste: 3(-0.417,0) 8(0.417,0)
  rrect25% 0.565x0.4 smd paste-0.2: 3(-0.417,0) 8(0.417,0)
  body extent -0.55,-1.3 0.55,1.3, height 0.56
DQA0010A#2 [mm] "SON, 10-Leads, Body 1x2.5mm, Pitch 0.5mm, TI Recommended"
  rrect50% 0.565x0.2 smd: 1(-0.417,1) 2(-0.417,0.5) 4(-0.417,-0.5) 5(-0.417,-1) 6(0.417,-1) 7(0.417,-0.5) 9(0.417,0.5) 10(0.417,1)
  rrect28% 0.565x0.36 on Bottom Paste: 3(-0.417,0) 8(0.417,0)
  rrect25% 0.565x0.4 smd paste-0.2: 3(-0.417,0) 8(0.417,0)
  body extent -0.55,-1.3 0.55,1.3, height 0.56
DYY0016A [mm] "SOP, 16-Leads, Body 2x4.2mm, Pitch 0.5mm"
  rrect33% 1.05x0.3 smd: 1(-1.5,1.75) 2(-1.5,1.25) 3(-1.5,0.75) 4(-1.5,0.25) 5(-1.5,-0.25) 6(-1.5,-0.75) 7(-1.5,-1.25) 8(-1.5,-1.75) 9(1.5,-1.75) 10(1.5,-1.25) 11(1.5,-0.75) 12(1.5,-0.25) 13(1.5,0.25) 14(1.5,0.75) 15(1.5,1.25) 16(1.5,1.75)
  body extent -1.63,-2.1 1.63,2.1, height 1.02
ESD_Overlay_Medium [mil]
  silkscreen extent -127,-109 125,110
FCC_disclaimer [mil]
Fiducial10-20 [mm]
  round 1 smd mask+0.5: 1(0,0)
  Top Layer keep-out circle w1.178: c0,0 r0.5
FP-132134-10_SMA-MFG [mm]
  round 1.73 smd paste+0 mask+0: 1(0,0)
  round 2.115 smd paste+0 mask+0: 2(-2.38,2.32) 3(2.38,-2.38)
  Top Layer region: 1.205,-3.555 3.555,-3.555 3.555,3.555 1.205,3.555 1.205,1.652 1.823,0.927 2.045,0 1.823,-0.927 1.205,-1.652 1.205,-1.652
  Top Layer region: -1.205,-3.555 -3.555,-3.555 -3.555,3.555 -1.205,3.555 -1.205,1.652 -1.823,0.927 -2.045,0 -1.823,-0.927 -1.205,-1.652 -1.205,-1.652
  body extent -3.66,-3.66 3.66,3.66, height 0.25
FP-APHHS1005LSECK/J3-PF_0402-MFG [mm]
  rrect20% 0.7x0.5 smd paste+0 mask+0: 1(-0.45,0) 2(0.45,0)
  body extent -0.9,-0.4 0.9,0.4, height 0.25
FP-APHHS1005LSECK/J4-PF_0402-MFG [mm]
  rrect20% 0.7x0.5 smd paste+0 mask+0: 1(-0.45,0) 2(0.45,0)
  body extent -0.9,-0.4 0.9,0.4, height 0.25
FP-APHHS1005LZGCK-V_0402-MFG [mm]
  rrect20% 0.7x0.5 smd paste+0 mask+0: 1(-0.45,0) 2(0.45,0)
  body extent -0.9,-0.4 0.9,0.4, height 0.25
FP-BLM18HE152SH1D_0603-MFG [mm]
  rrect15% 0.65x0.7 smd paste+0 mask+0: 1(-0.675,0) 2(0.675,0)
  body extent -1.1,-0.58 1.1,0.58, height 0.25
FP-CAT24C08TDI-GT3_TSOT-23-5-IPC_C [mm]
  rrect21% 0.94x0.486 smd paste+0 mask+0: 1(-1.115,0.95)
  rrect100% 0.94x0.486 smd paste+0 mask+0: 2(-1.115,0) 3(-1.115,-0.95) 4(1.116,-0.95) 5(1.116,0.95)
  body extent -1.69,-1.55 1.69,1.55, height 0.25
FP-CX2016DB48000C0FRLC1_SMT4_2MM05_1MM65-MFG [mil]
  round 19.93 smd paste+0 mask+0: 1(-32.23,-24.36) 2(32.23,-24.36) 3(32.23,24.36) 4(-32.23,24.36)
  Top Layer region: -25.2,-10.63 -24.14,-14.57 -21.26,-17.45 -17.32,-18.5 -17.32,-18.5 -13.78,-18.5 -13.78,-35.43 -43.31,-35.43 -43.31,-5.91 -25.2,-5.91
  Top Layer region: 25.2,-10.63 24.14,-14.57 21.26,-17.45 17.32,-18.5 17.32,-18.5 13.78,-18.5 13.78,-35.43 43.31,-35.43 43.31,-5.91 25.2,-5.91
  Top Layer region: -25.2,10.63 -24.6,13.64 -22.89,16.2 -20.34,17.9 -17.32,18.5 -17.32,18.5 -13.78,18.5 -13.78,35.43 -43.31,35.43 -43.31,5.91 -25.2,5.91
  Top Layer region: 25.2,10.63 24.6,13.64 22.89,16.2 20.34,17.9 17.32,18.5 17.32,18.5 13.78,18.5 13.78,35.43 43.31,35.43 43.31,5.91 25.2,5.91
  silkscreen extent -61,-49 -51,-40, body extent -47,-39 47,39, height 10
FP-DCB-12D_SPACER-MFG [mm]
  round 3 hole 3 unplated paste-2539.97 mask+0: ""(0,0)
  body extent -3.75,-3.25 3.75,3.25, height 0.25
"FP-DST1610A 7BG03276AAC_SMD2-MFG" [mm]
  rrect14% 0.7x1.2 smd paste+0 mask+0: 1(-0.55,0) 2(0.55,0)
  body extent -1,-0.7 1,0.7, height 0.25
FP-GCM32ER71E106MA57L_1210-MFG [mm]
  rrect9% 1.1x2.05 smd paste+0 mask+0: 1(-1.65,0) 2(1.65,0)
  body extent -2.3,-1.45 2.3,1.45, height 0.25
FP-GCM155R71E473KA55D_0402-MFG [mm]
  rrect25% 0.4x0.5 smd paste+0 mask+0: 1(-0.4,0) 2(0.4,0)
  body extent -0.5,-0.25 0.5,0.25, height 0.55
FP-GCQ0335C1H1R0BB01D_0201-MFG [mm]
  rrect40% 0.25x0.3 smd paste+0 mask+0: 1(-0.238,0) 2(0.238,0)
  body extent -0.46,-0.27 0.46,0.27, height 0.25
FP-GCQ0335C1H1R0WB01D_0201-MFG [mm]
  rrect40% 0.25x0.3 smd paste+0 mask+0: 1(-0.238,0) 2(0.238,0)
  body extent -0.46,-0.27 0.46,0.27, height 0.25
FP-GCQ0335C1H120GB01D_0201-MFG [mm]
  rrect40% 0.25x0.3 smd paste+0 mask+0: 1(-0.238,0) 2(0.238,0)
  body extent -0.46,-0.27 0.46,0.27, height 0.25
FP-GCQ0335C1HR70WB01D_0201-MFG [mm] "Recommended Land Pattern"
  rrect40% 0.25x0.3 smd paste+0 mask+0: 1(-0.238,0) 2(0.238,0)
  body extent -0.46,-0.27 0.46,0.27, height 0.25
"FP-LQP03TN1N9BZ2B_0201 (0603)-MFG" [mm] "Recommended Land Pattern"
  rrect40% 0.3x0.25 smd paste+0 mask+0: 1(-0.275,0) 2(0.275,0)
  body extent -0.53,-0.27 0.53,0.27, height 0.25
"FP-LQP03TN3N4BZ2B_0201 (0603)-MFG" [mm]
  rrect40% 0.3x0.25 smd paste+0 mask+0: 1(-0.275,0) 2(0.275,0)
  body extent -0.53,-0.27 0.53,0.27, height 0.25
FP-LQP03TN3N7BZ2J_0603-MFG [mm]
  rrect40% 0.3x0.25 smd paste+0 mask+0: 1(-0.275,0) 2(0.275,0)
  body extent -0.53,-0.27 0.53,0.27, height 0.25
FP-MLZ2012N6R8LTD25_0805-MFG [mm]
  rrect13% 0.8x1.2 smd paste+0 mask+0: 1(-0.9,0) 2(0.9,0)
  body extent -1.4,-0.82 1.4,0.82, height 0.25
FP-SMS-403C_RF_SHLD-MFG [mil]
  body extent -535,-535 535,535, height 10
FP-SMS-403F_SMT_SHIELD-MFG [mil]
  round 40.65 smd paste+0 mask+0: 1(-508.97,508.97) 5(508.97,508.97) 12(-508.97,-508.97) 16(508.97,-508.97)
  rrect10% 147x39 smd paste+0 mask+0: 2(-236.5,512.5) 3(-0.5,512.5) 4(235.5,512.5) 13(-236.5,-512.5) 14(-0.5,-512.5) 15(235.5,-512.5)
  rrect10% 39x147 smd paste+0 mask+0: 6(-512.5,235.5) 7(512.5,235.5) 8(-512.5,-0.5) 9(512.5,-0.5) 10(-512.5,-236.5) 11(512.5,-236.5)
  Top Layer region: -532,532 -398,532 -398,493 -493,493 -493,398 -532,398
  Top Layer region: 532,532 532,398 493,398 493,493 398,493 398,532
  Top Layer region: -532,-532 -532,-398 -493,-398 -493,-493 -398,-493 -398,-532
  Top Layer region: 532,-532 532,-398 493,-398 493,-493 398,-493 398,-532
  body extent -536,-536 536,536, height 10
Keystone1598-2 [mm] "Triple Turret"
  round 3.5 hole 2.5: 1(0,0)
  body extent -1.6,-1.6 1.59,1.6, height 7.72
Keystone5012 [mil] "Keystone Multipurpose loops"
  round 87 hole 63: 1(0,0)
  body extent -63,-63 63,62, height 319
RGZ0048R-MFG [mm]
  rrect40% 0.6x0.25 smd paste+0 mask+0: 1(-3.4,2.75) 2(-3.4,2.25) 3(-3.4,1.75) 4(-3.4,1.25) 5(-3.4,0.75) 6(-3.4,0.25) 7(-3.4,-0.25) 8(-3.4,-0.75) 9(-3.4,-1.25) 10(-3.4,-1.75) 11(-3.4,-2.25) 12(-3.4,-2.75) 25(3.4,-2.75) 26(3.4,-2.25) 27(3.4,-1.75) 28(3.4,-1.25) 29(3.4,-0.75) 30(3.4,-0.25) 31(3.4,0.25) 32(3.4,0.75) 33(3.4,1.25) 34(3.4,1.75) 35(3.4,2.25) 36(3.4,2.75)
  rrect40% 0.25x0.6 smd paste+0 mask+0: 13(-2.75,-3.4) 14(-2.25,-3.4) 15(-1.75,-3.4) 16(-1.25,-3.4) 17(-0.75,-3.4) 18(-0.25,-3.4) 19(0.25,-3.4) 20(0.75,-3.4) 21(1.25,-3.4) 22(1.75,-3.4) 23(2.25,-3.4) 24(2.75,-3.4) 37(2.75,3.4) 38(2.25,3.4) 39(1.75,3.4) 40(1.25,3.4) 41(0.75,3.4) 42(0.25,3.4) 43(-0.25,3.4) 44(-0.75,3.4) 45(-1.25,3.4) 46(-1.75,3.4) 47(-2.25,3.4) 48(-2.75,3.4)
  rrect2% 5.15x5.15 smd paste-1000 mask+0: 49(0,0)
  silkscreen extent -4.07,-3.55 3.55,3.55, body extent -3.8,-3.8 3.8,3.8, height 0.25
Samtec_FTSH-105-01-x-DV-K [mm] "Header(Shrouded), 1.27mm, 5x2, SMT"
  rect 2.79x0.74 smd: 1(-2.035,2.54) 2(2.035,2.54) 3(-2.035,1.27) 4(2.035,1.27) 5(-2.035,0) 6(2.035,0) 7(-2.035,-1.27) 8(2.035,-1.27) 9(-2.035,-2.54) 10(2.035,-2.54)
  body extent -2.92,-3.18 2.92,3.17, height 6.13
SNT-100-BK-G [mil] "Samtec STEP model"
  round 1 on Mech3: 0(0,0)
  body extent -100,-50 100,50, height 344
Sullins_SFH11-xxxC-D10-RA [mm] "Receptacle, 2.54mm, 10x2, R/A, TH"
  rrect50% 1.53x1.53 hole 1.02: 1(-11.43,1.27)
  round 1.53 hole 1.02: 2(-11.43,-1.27) 3(-8.89,1.27) 4(-8.89,-1.27) 5(-6.35,1.27) 6(-6.35,-1.27) 7(-3.81,1.27) 8(-3.81,-1.27) 9(-1.27,1.27) 10(-1.27,-1.27) 11(1.27,1.27) 12(1.27,-1.27) 13(3.81,1.27) 14(3.81,-1.27) 15(6.35,1.27) 16(6.35,-1.27) 17(8.89,1.27) 18(8.89,-1.27) 19(11.43,1.27) 20(11.43,-1.27)
  body extent -15.24,-11.37 15.24,1.47, height 7
SW_CL-SA-12C-22 [mm] "SMD, 3-Leads, Body 10x2.54mm, Pitch 2.54mm"
  rrect50% 1.5x1.5 hole 1: 1(0,0)
  round 1.5 hole 1: 2(-2.54,0) 3(2.54,0)
  body extent -5,-1.27 5,1.27, height 6.4
TI_Stacked_Overlay_Small [mil]
  silkscreen extent -418,-98 418,98
TP_SM_1MM#1 [mm] "1mm Test Point, SMT"
  round 1 smd paste-0.5: 1(0,0)
TP_SM_1MM#2 [mm] "1mm Test Point, SMT"
  round 1 smd paste-0.5: 1(0.076,0)
TP_SM_1MM#3 [mm] "1mm Test Point, SMT"
  round 1 smd paste-0.5: 1(-0.991,0)
TP_SM_1MM#4 [mm] "1mm Test Point, SMT"
  round 1 smd paste-0.5: 1(0,1.321)
TSW-102-07-G-S [mm] "Samtec 100mil, 1x2, 230 mil above insulator"
  rrect50% 1.65x1.65 hole 1.016: 1(-1.27,0)
  round 1.65 hole 1.016: 2(1.27,0)
  silkscreen extent -3.17,-0.13 -2.92,0.13, body extent -2.54,-1.27 2.54,1.27, height 8.38
TSW-103-07-G-D [mm] "Samtec 100mil, 2x3, 230 mil above insulator"
  rect 1.65x1.65 hole 1.016: 1(-2.54,-1.27)
  round 1.65 hole 1.016: 2(-2.54,1.27) 3(0,-1.27) 4(0,1.27) 5(2.54,-1.27) 6(2.54,1.27)
  silkscreen extent -4.83,-2.52 -4.59,-2.27, body extent -3.81,-2.54 3.81,2.54, height 8.38
TSW-104-07-G-S [mm] "Samtec 100mil, 1x4, 230 mil above insulator"
  rrect50% 1.65x1.65 hole 1.016: 1(-3.81,0)
  round 1.65 hole 1.016: 2(-1.27,0) 3(1.27,0) 4(3.81,0)
  body extent -5.08,-1.27 5.08,1.27, height 8.38
TSW-113-07-G-D [mm] "Samtec 100mil, 2x13, 230 mil above insulator"
  rrect6% 1.65x1.65 hole 1.016: 1(-15.24,-1.27)
  round 1.65 hole 1.016: 2(-15.24,1.27) 3(-12.7,-1.27) 4(-12.7,1.27) 5(-10.16,-1.27) 6(-10.16,1.27) 7(-7.62,-1.27) 8(-7.62,1.27) 9(-5.08,-1.27) 10(-5.08,1.27) 11(-2.54,-1.27) 12(-2.54,1.27) 13(0,-1.27) 14(0,1.27) 15(2.54,-1.27) 16(2.54,1.27) 17(5.08,-1.27) 18(5.08,1.27) 19(7.62,-1.27) 20(7.62,1.27) 21(10.16,-1.27) 22(10.16,1.27) 23(12.7,-1.27) 24(12.7,1.27) 25(15.24,-1.27) 26(15.24,1.27)
  silkscreen extent -17.53,-2.52 -17.28,-2.28, body extent -16.51,-2.54 16.51,2.54, height 8.38
WEEE_Minimum [mil] "WEEElie bin"
  silkscreen extent -95,-172 99,104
